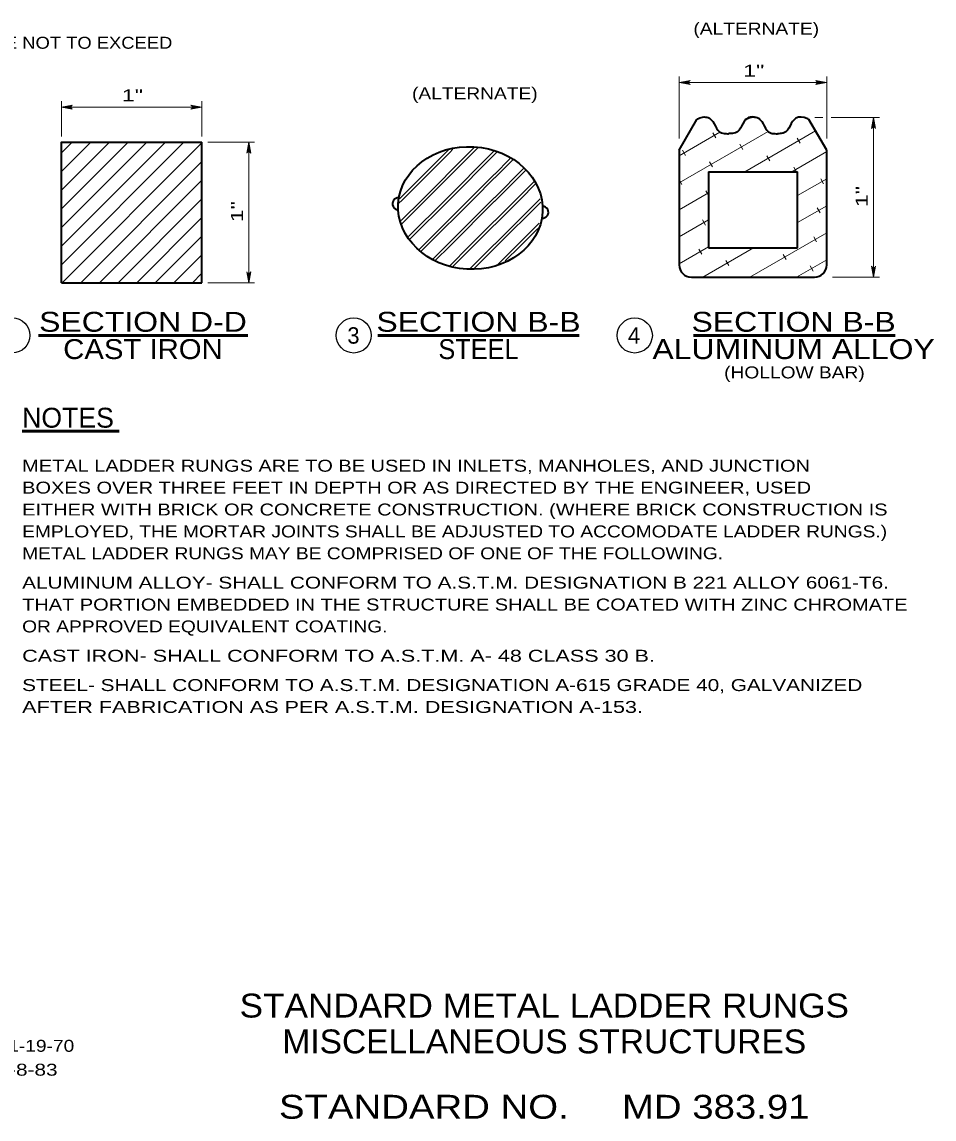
# Model space of a CAD drawing. Extents: x 16 to 133, y -56 to 112.
# Drawn here: x 55.4 to 133.2, y -55.6 to 38.1 of the extents above; entities that cross this region are included whole.
import ezdxf
from ezdxf.enums import TextEntityAlignment as Align

# ---------------------------------------------------------------- set-up
doc = ezdxf.new("R2010")
doc.units = 0
doc.header["$LTSCALE"] = 0.41
for name, color, linetype, lineweight in [('1', 7, 'Continuous', 35), ('10', 7, 'Continuous', 13), ('12', 7, 'Continuous', 53), ('13', 7, 'Continuous', 25), ('6', 7, 'Continuous', 13)]:
    doc.layers.add(name, color=color, linetype=linetype, lineweight=lineweight)

msp = doc.modelspace()

# ---------------------------------------------------------------- linework, layer by layer
at = {"layer": '1'}
for p, q in [((111.4602, 27.168), (112.9768, 29.7948)), ((124.0602, 27.168), (122.5442, 29.7937)), ((70.7175, 15.8375), (70.7175, 27.8375)), ((111.4602, 27.168), (111.4602, 17.368)), ((124.0602, 17.368), (124.0602, 27.168)), ((113.9602, 25.318), (113.9602, 18.818)), ((113.9602, 25.318), (121.5602, 25.318)), ((121.5602, 18.818), (121.5602, 25.318)), ((113.9602, 18.818), (121.5602, 18.818)), ((112.5102, 16.318), (123.0102, 16.318)), ((58.7175, 15.8375), (70.7175, 15.8375))]:
    msp.add_line(p, q, dxfattribs=at)
msp.add_lwpolyline([(58.7175, 15.8375), (58.7175, 27.8375), (70.7175, 27.8375)], dxfattribs=at)
for centre, radius, start, end in [((87.4812, 22.5872), 0.5, 83.40219, 269.85116), ((99.8008, 21.8611), 0.5, 263.40369, 89.85122), ((112.5102, 17.368), 1.05, 180, 270), ((123.0102, 17.368), 1.05, 270, 0)]:
    msp.add_arc(centre, radius, start, end, dxfattribs=at)
msp.add_ellipse((93.641, 22.2242), major_axis=(-6.1598, 0.3631), ratio=0.848332, dxfattribs=at)
for points in [[(112.96, 29.7843), (113.1151, 29.8813), (114.0569, 29.8887), (115.0761, 28.6423), (115.2933, 28.5974), (115.6747, 28.568)], [(118.3899, 29.7843), (118.2348, 29.8813), (117.293, 29.8887), (116.2738, 28.6423), (116.0055, 28.5953), (115.6747, 28.568)], [(117.1339, 29.7843), (117.289, 29.8813), (118.2308, 29.8887), (119.25, 28.6423), (119.4074, 28.6015), (119.8641, 28.568)], [(122.5441, 29.7937), (122.3721, 29.8813), (121.4303, 29.8887), (120.4111, 28.6423), (120.2881, 28.6066), (119.8641, 28.568)]]:
    msp.add_spline(points, degree=3, dxfattribs=at)
at = {"layer": '10'}
for p, q in [((111.4602, 28.168), (111.4602, 33.4422)), ((111.4602, 32.9422), (124.0602, 32.9422)), ((124.0602, 28.1679), (124.0602, 33.4422)), ((58.7175, 28.3375), (58.7175, 31.3375)), ((70.7175, 28.3375), (70.7175, 31.3375)), ((58.7175, 30.8375), (70.7175, 30.8375)), ((123.0358, 29.9422), (123.7325, 29.9422)), ((124.4321, 29.9422), (128.5602, 29.9422)), ((128.0602, 16.318), (128.0602, 29.9422)), ((71.2175, 27.8375), (75.2175, 27.8375)), ((74.7175, 15.8375), (74.7175, 27.8375)), ((124.5602, 16.318), (128.5602, 16.318)), ((71.2175, 15.8375), (75.2175, 15.8375))]:
    msp.add_line(p, q, dxfattribs=at)
for points in [[(111.4602, 32.9422), (112.3922, 33.117), (112.3204, 33.0672), (112.2834, 33.0047), (112.2727, 32.9422), (112.2834, 32.8797), (112.3204, 32.8172), (112.3922, 32.7675), (111.4602, 32.9422), (112.3204, 32.8172), (112.2834, 32.8797), (111.4602, 32.9422), (112.2727, 32.9422), (112.2834, 33.0047), (111.4602, 32.9422), (112.3204, 33.0672)], [(124.0602, 32.9422), (123.1281, 32.7675), (123.1999, 32.8172), (123.237, 32.8797), (123.2477, 32.9422), (123.237, 33.0047), (123.1999, 33.0672), (123.1281, 33.117), (124.0602, 32.9422), (123.1999, 33.0672), (123.237, 33.0047), (124.0602, 32.9422), (123.2477, 32.9422), (123.237, 32.8797), (124.0602, 32.9422), (123.1999, 32.8172)], [(58.7175, 30.8375), (59.6496, 31.0123), (59.5778, 30.9625), (59.5408, 30.9), (59.53, 30.8375), (59.5408, 30.775), (59.5778, 30.7125), (59.6496, 30.6628), (58.7175, 30.8375), (59.5778, 30.7125), (59.5408, 30.775), (58.7175, 30.8375), (59.53, 30.8375), (59.5408, 30.9), (58.7175, 30.8375), (59.5778, 30.9625)], [(70.7175, 30.8375), (69.7855, 30.6628), (69.8573, 30.7125), (69.8943, 30.775), (69.905, 30.8375), (69.8943, 30.9), (69.8573, 30.9625), (69.7855, 31.0123), (70.7175, 30.8375), (69.8573, 30.9625), (69.8943, 30.9), (70.7175, 30.8375), (69.905, 30.8375), (69.8943, 30.775), (70.7175, 30.8375), (69.8573, 30.7125)], [(128.0602, 29.9422), (128.2349, 29.0102), (128.1852, 29.082), (128.1227, 29.119), (128.0602, 29.1297), (127.9977, 29.119), (127.9352, 29.082), (127.8854, 29.0102), (128.0602, 29.9422), (127.9352, 29.082), (127.9977, 29.119), (128.0602, 29.9422), (128.0602, 29.1297), (128.1227, 29.119), (128.0602, 29.9422), (128.1852, 29.082)], [(74.7175, 27.8375), (74.8923, 26.9054), (74.8425, 26.9773), (74.78, 27.0143), (74.7175, 27.025), (74.655, 27.0143), (74.5925, 26.9773), (74.5428, 26.9054), (74.7175, 27.8375), (74.5925, 26.9773), (74.655, 27.0143), (74.7175, 27.8375), (74.7175, 27.025), (74.78, 27.0143), (74.7175, 27.8375), (74.8425, 26.9773)], [(128.0602, 16.318), (127.8854, 17.25), (127.9352, 17.1782), (127.9977, 17.1412), (128.0602, 17.1305), (128.1227, 17.1412), (128.1852, 17.1782), (128.2349, 17.25), (128.0602, 16.318), (128.1852, 17.1782), (128.1227, 17.1412), (128.0602, 16.318), (128.0602, 17.1305), (127.9977, 17.1412), (128.0602, 16.318), (127.9352, 17.1782)], [(74.7175, 15.8375), (74.5428, 16.7696), (74.5925, 16.6978), (74.655, 16.6607), (74.7175, 16.65), (74.78, 16.6607), (74.8425, 16.6978), (74.8923, 16.7696), (74.7175, 15.8375), (74.8425, 16.6978), (74.78, 16.6607), (74.7175, 15.8375), (74.7175, 16.65), (74.655, 16.6607), (74.7175, 15.8375), (74.5925, 16.6978)]]:
    msp.add_lwpolyline(points, dxfattribs=at)
at = {"layer": '12'}
for p, q in [((56.7817, 11.3401), (74.6534, 11.3401)), ((85.7401, 11.3401), (102.9259, 11.3401)), ((112.6749, 11.3401), (129.897, 11.3401))]:
    msp.add_line(p, q, dxfattribs=at)
at = {"layer": '13', "lineweight": 53}
msp.add_line((55.3721, 3.1728), (63.6453, 3.1728), dxfattribs=at)
at = {"layer": '13'}
for centre in [(54.5317, 11.3401), (83.6833, 11.3401), (107.6749, 11.3401)]:
    msp.add_circle(centre, 1.5, dxfattribs=at)
at = {"layer": '6'}
for p, q in [((111.4602, 24.383), (119.0517, 28.766)), ((111.4602, 26.6924), (114.9431, 28.7033)), ((114.6016, 28.2174), (114.3516, 28.6504)), ((117.0796, 25.318), (123.1161, 28.8031)), ((121.7978, 27.7533), (121.5478, 28.1863)), ((58.7912, 26.9856), (59.5848, 27.7792)), ((59.7539, 26.3573), (61.1758, 27.7792)), ((61.3449, 26.3573), (62.7667, 27.7792)), ((62.9359, 26.3573), (64.3577, 27.7792)), ((64.5268, 26.3573), (65.9487, 27.7792)), ((66.1178, 26.3573), (67.5397, 27.7792)), ((67.7089, 26.3573), (69.1307, 27.7792)), ((69.2998, 26.3573), (70.6411, 27.6986)), ((91.5399, 26.9616), (91.7646, 27.1863)), ((91.8732, 26.9616), (92.1505, 27.2388)), ((93.5399, 26.9616), (93.9903, 27.412)), ((93.8732, 26.9616), (94.2671, 27.3555)), ((116.9007, 27.2354), (116.6507, 27.6684)), ((58.7912, 25.3946), (59.7539, 26.3573)), ((59.7539, 24.7663), (61.3449, 26.3573)), ((59.7539, 23.1753), (62.9359, 26.3573)), ((59.7539, 21.5844), (64.5268, 26.3573)), ((59.7539, 19.9933), (66.1179, 26.3573)), ((59.7539, 18.4023), (67.7089, 26.3573)), ((59.7539, 16.8114), (69.2998, 26.3573)), ((87.6003, 23.022), (91.5399, 26.9616)), ((87.8732, 22.9616), (91.8732, 26.9616)), ((89.5399, 22.9616), (93.5399, 26.9616)), ((89.8732, 22.9616), (93.8732, 26.9616)), ((91.5399, 22.9616), (95.5399, 26.9616)), ((91.8732, 22.9616), (95.7066, 26.7949)), ((95.5399, 26.9616), (95.6512, 27.0729)), ((95.8806, 26.9616), (95.7066, 26.7876)), ((95.714, 25.1283), (97.0164, 26.4307)), ((97.223, 26.304), (95.714, 24.7949)), ((95.8806, 26.9616), (95.9341, 27.0151)), ((112.0035, 26.7174), (111.7535, 27.1504)), ((119.1997, 26.2533), (118.9497, 26.6863)), ((121.0796, 25.318), (124.0602, 27.0388)), ((60.4332, 15.8997), (70.6411, 26.1076)), ((95.714, 23.1283), (98.2095, 25.6239)), ((95.8806, 22.9616), (98.3506, 25.4316)), ((114.3026, 25.7354), (114.0526, 26.1684)), ((121.4718, 25.318), (121.2487, 25.7043)), ((58.7912, 23.8037), (59.7539, 24.7663)), ((62.0242, 15.8997), (70.6411, 24.5166)), ((93.5399, 22.9616), (95.7066, 25.1283)), ((93.8732, 22.9616), (95.7066, 24.7949)), ((97.5473, 22.9616), (99.0561, 24.4705)), ((111.7045, 24.2354), (111.4602, 24.6586)), ((121.5602, 23.286), (124.0602, 24.7294)), ((123.7978, 24.2892), (123.5478, 24.7222)), ((97.8806, 22.9616), (99.1972, 24.2782)), ((111.4602, 22.0736), (113.9602, 23.517)), ((114.0035, 23.2533), (113.7535, 23.6863)), ((58.7912, 22.2127), (59.7539, 23.1753)), ((63.6152, 15.8997), (70.6411, 22.9256)), ((87.4838, 22.5722), (87.8732, 22.9616)), ((87.7316, 21.1533), (89.5399, 22.9616)), ((87.7812, 20.8695), (89.8732, 22.9616)), ((88.3689, 19.7906), (91.5399, 22.9616)), ((88.5064, 19.5948), (91.8732, 22.9616)), ((89.5399, 18.9616), (93.5399, 22.9616)), ((89.8732, 18.9616), (93.8732, 22.9616)), ((91.5399, 18.9616), (95.5399, 22.9616)), ((91.8732, 18.9616), (95.7066, 22.7949)), ((95.5399, 22.9616), (95.7066, 23.1283)), ((95.8806, 22.9616), (95.7066, 22.7876)), ((95.714, 19.1283), (99.5473, 22.9616)), ((97.8806, 22.9616), (95.714, 20.7949)), ((95.714, 21.1283), (97.5473, 22.9616)), ((95.8806, 18.9616), (99.653, 22.734)), ((99.5473, 22.9616), (99.5978, 23.0121)), ((58.7912, 20.6217), (59.7539, 21.5844)), ((121.5602, 20.9766), (124.0602, 22.42)), ((123.4987, 21.8072), (123.2487, 22.2402)), ((65.2062, 15.8997), (70.6411, 21.3347)), ((93.5399, 18.9616), (95.7066, 21.1283)), ((93.8732, 18.9616), (95.7066, 20.7949)), ((97.5473, 18.9616), (99.5244, 20.9387)), ((111.4602, 19.7642), (113.9602, 21.2076)), ((113.7045, 20.7713), (113.4545, 21.2043)), ((58.7912, 19.0307), (59.7539, 19.9934)), ((66.7972, 15.8997), (70.6411, 19.7437)), ((97.8806, 18.9616), (99.3986, 20.4796)), ((117.4911, 16.318), (124.0602, 20.1106)), ((123.1997, 19.3251), (122.9497, 19.7581)), ((89.2446, 18.6663), (89.5399, 18.9616)), ((89.4479, 18.5363), (89.8732, 18.9616)), ((90.4647, 17.8864), (91.5399, 18.9616)), ((90.668, 17.7564), (91.8732, 18.9616)), ((91.9045, 17.3262), (93.5399, 18.9616)), ((92.1773, 17.2656), (93.8732, 18.9616)), ((93.5976, 17.0193), (95.5399, 18.9616)), ((93.9757, 17.0641), (95.7066, 18.7949)), ((95.5399, 18.9616), (95.7066, 19.1283)), ((95.8806, 18.9616), (95.7066, 18.7876)), ((95.9449, 17.3592), (97.5473, 18.9616)), ((97.8806, 18.9616), (96.6217, 17.7027)), ((111.4602, 17.4548), (113.9602, 18.8982)), ((113.4911, 16.318), (117.8213, 18.818)), ((58.7912, 17.4397), (59.7539, 18.4024)), ((68.3882, 15.8997), (70.6411, 18.1526)), ((113.4055, 18.2892), (113.1555, 18.7222)), ((120.6016, 17.8251), (120.3516, 18.2581)), ((115.7045, 17.3072), (115.4545, 17.7402)), ((121.4911, 16.318), (124.0602, 17.8012)), ((122.9007, 16.8431), (122.6507, 17.2761)), ((58.8422, 15.8997), (59.7539, 16.8114)), ((69.9792, 15.8997), (70.6411, 16.5617))]:
    msp.add_line(p, q, dxfattribs=at)

# ---------------------------------------------------------------- texts
at = {"layer": '12'}
for s, height, width, p in [('(ALTERNATE)', 1.02, 1.2, (118.0462, 37.0411)), ('(ALTERNATE)', 1.02, 1.2, (94.0207, 31.5066)), ('SECTION D-D', 1.7, 1.2, (65.686, 11.6563)), ('SECTION B-B', 1.7, 1.2, (94.3313, 11.6563)), ('SECTION B-B', 1.7, 1.2, (121.2347, 11.6563)), ('CAST IRON', 1.7, 1.1, (65.686, 9.3239)), ('STEEL', 1.7, 0.95, (94.3313, 9.3239)), ('ALUMINUM ALLOY', 1.7, 1.2, (121.2347, 9.3239)), ('(HOLLOW BAR)', 1.02, 1.2, (121.3064, 7.6732))]:
    msp.add_text(s, height=height, dxfattribs=dict(at, width=width)).set_placement(p, align=Align.CENTER)
at = {"layer": '12', "width": 1.15}
msp.add_text('GROOVES ARE NOT TO EXCEED', height=1.02, dxfattribs=at).set_placement((43.3534, 35.8283))
at = {"layer": '13'}
for s, height, width, p in [('1"', 1.02, 1.45, (117.8319, 33.4422)), ('1"', 1.02, 1.45, (64.7892, 31.3375)), ('STANDARD METAL LADDER RUNGS', 2.04, 1.1, (99.9475, -46.9125)), ('MISCELLANEOUS STRUCTURES', 2.04, 1.05, (99.9475, -49.9725)), ('STANDARD NO.     MD 383.91', 2.04, 1.2, (99.9475, -55.5538))]:
    msp.add_text(s, height=height, dxfattribs=dict(at, width=width)).set_placement(p, align=Align.CENTER)
at = {"layer": '13', "width": 1.45}
for p in [(127.5602, 23.2018), (74.2175, 21.9092)]:
    msp.add_text('1"', height=1.02, rotation=90, dxfattribs=at).set_placement(p, align=Align.CENTER)
at = {"layer": '13'}
for s, p in [('3', (83.6567, 10.6401)), ('4', (107.6143, 10.6401))]:
    msp.add_text(s, height=1.4, dxfattribs=at).set_placement(p, align=Align.CENTER)
msp.add_text('NOTES', height=1.7, dxfattribs=at).set_placement((55.3721, 3.4635))
for s, width, p in [('METAL LADDER RUNGS ARE TO BE USED IN INLETS, MANHOLES, AND JUNCTION', 1.25, (55.3721, -0.2961)), ('BOXES OVER THREE FEET IN DEPTH OR AS DIRECTED BY THE ENGINEER, USED', 1.25, (55.3721, -2.1661)), ('EITHER WITH BRICK OR CONCRETE CONSTRUCTION. (WHERE BRICK CONSTRUCTION IS', 1.25, (55.3721, -4.0361)), ('EMPLOYED, THE MORTAR JOINTS SHALL BE ADJUSTED TO ACCOMODATE LADDER RUNGS.)', 1.2, (55.3721, -5.9061)), ('METAL LADDER RUNGS MAY BE COMPRISED OF ONE OF THE FOLLOWING.', 1.2, (55.3721, -7.7761)), ('ALUMINUM ALLOY- SHALL CONFORM TO A.S.T.M. DESIGNATION B 221 ALLOY 6061-T6.', 1.3, (55.3721, -10.2802)), ('THAT PORTION EMBEDDED IN THE STRUCTURE SHALL BE COATED WITH ZINC CHROMATE', 1.25, (55.3721, -12.1502)), ('OR APPROVED EQUIVALENT COATING.', 1.2, (55.3721, -14.0202)), ('CAST IRON- SHALL CONFORM TO A.S.T.M. A- 48 CLASS 30 B.', 1.35, (55.3721, -16.5243)), ('STEEL- SHALL CONFORM TO A.S.T.M. DESIGNATION A-615 GRADE 40, GALVANIZED', 1.3, (55.3721, -19.0284)), ('AFTER FABRICATION AS PER A.S.T.M. DESIGNATION A-153.', 1.35, (55.3721, -20.8984)), ('11-19-70', 1.2, (53.2707, -49.8382)), ('2-8-83', 1.3, (53.2707, -51.8783))]:
    msp.add_text(s, height=1.02, dxfattribs=dict(at, width=width)).set_placement(p)

doc.saveas('drawing.dxf')
